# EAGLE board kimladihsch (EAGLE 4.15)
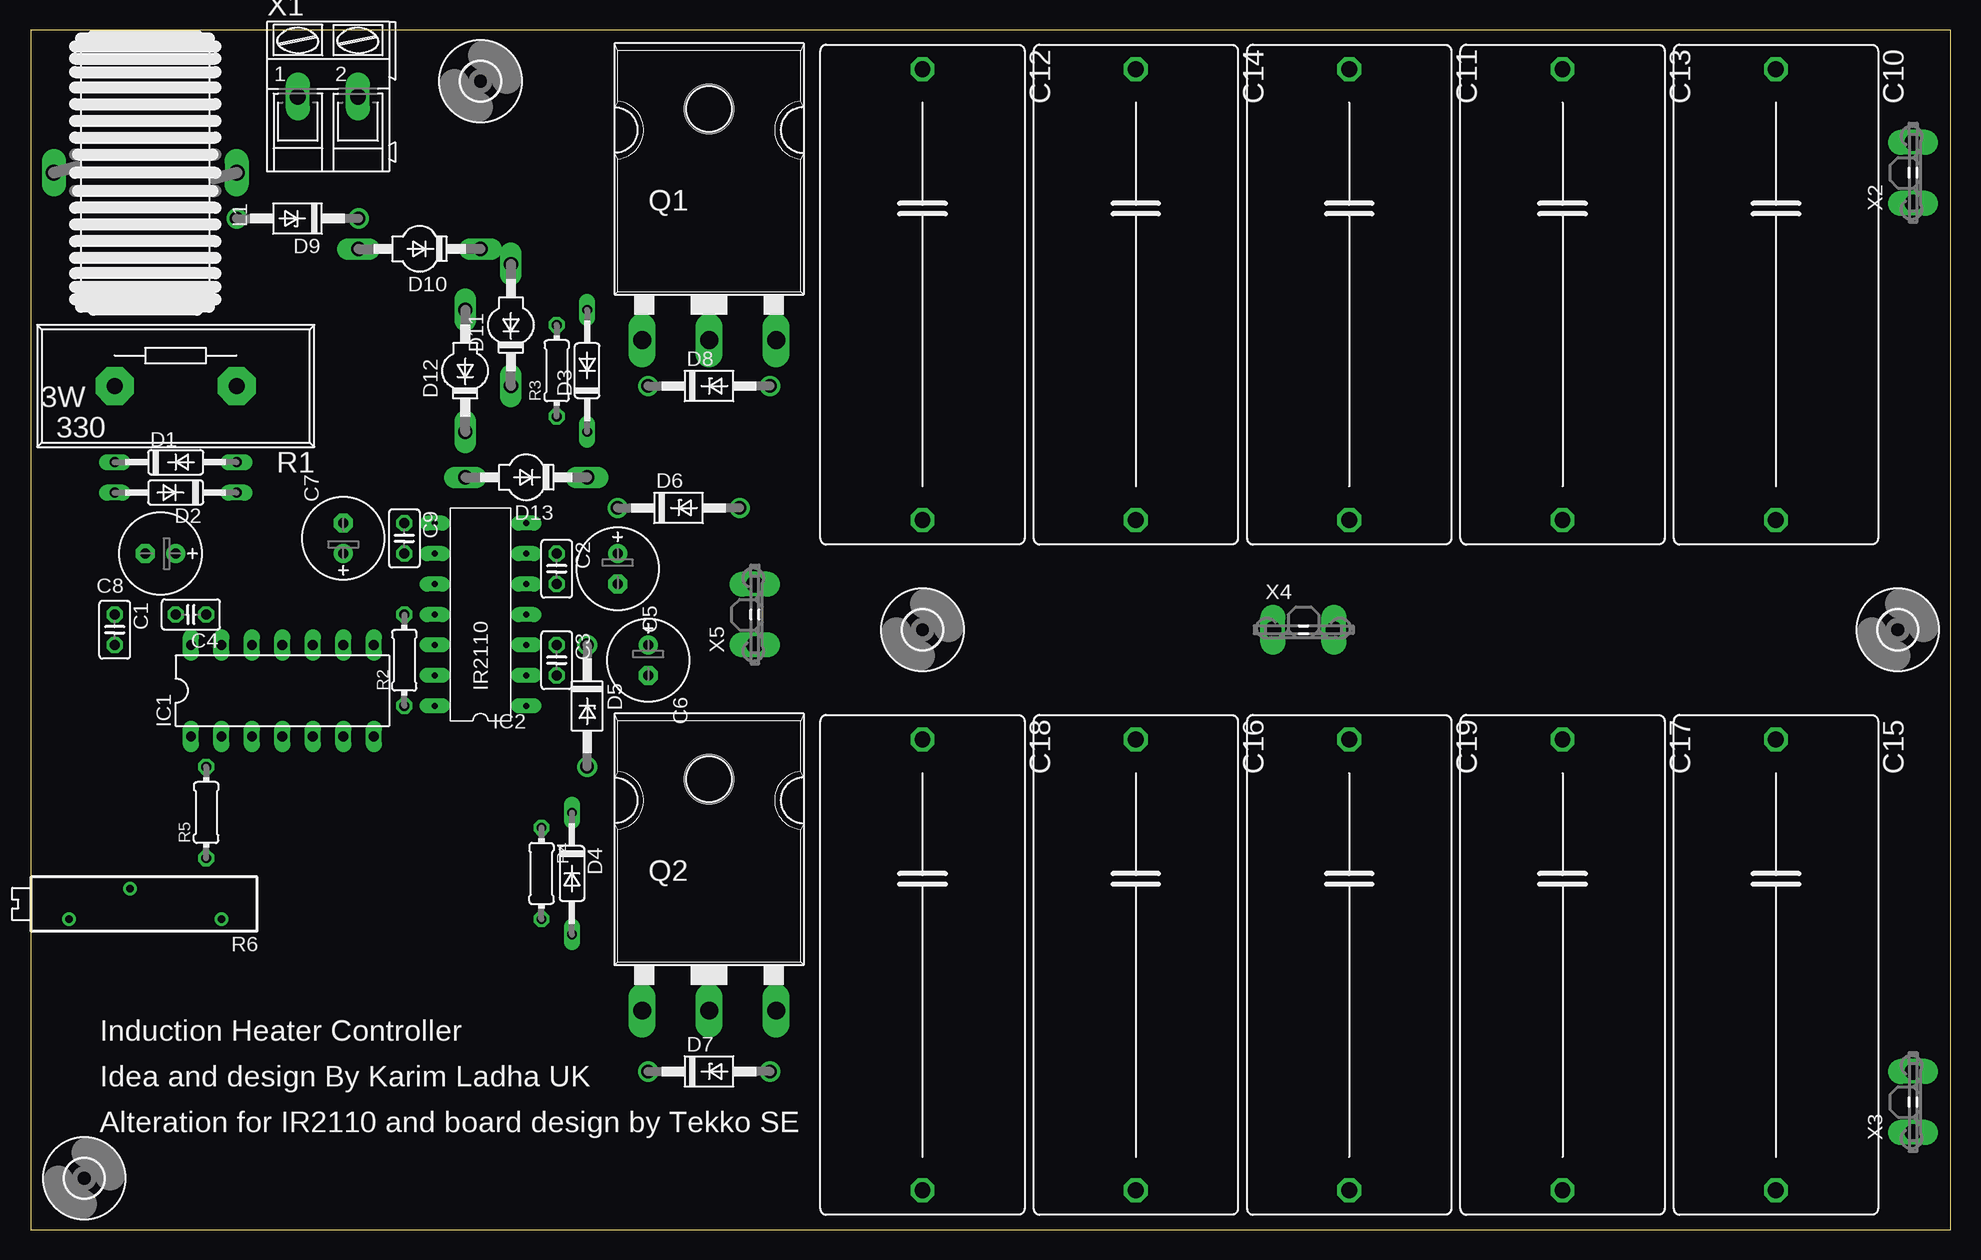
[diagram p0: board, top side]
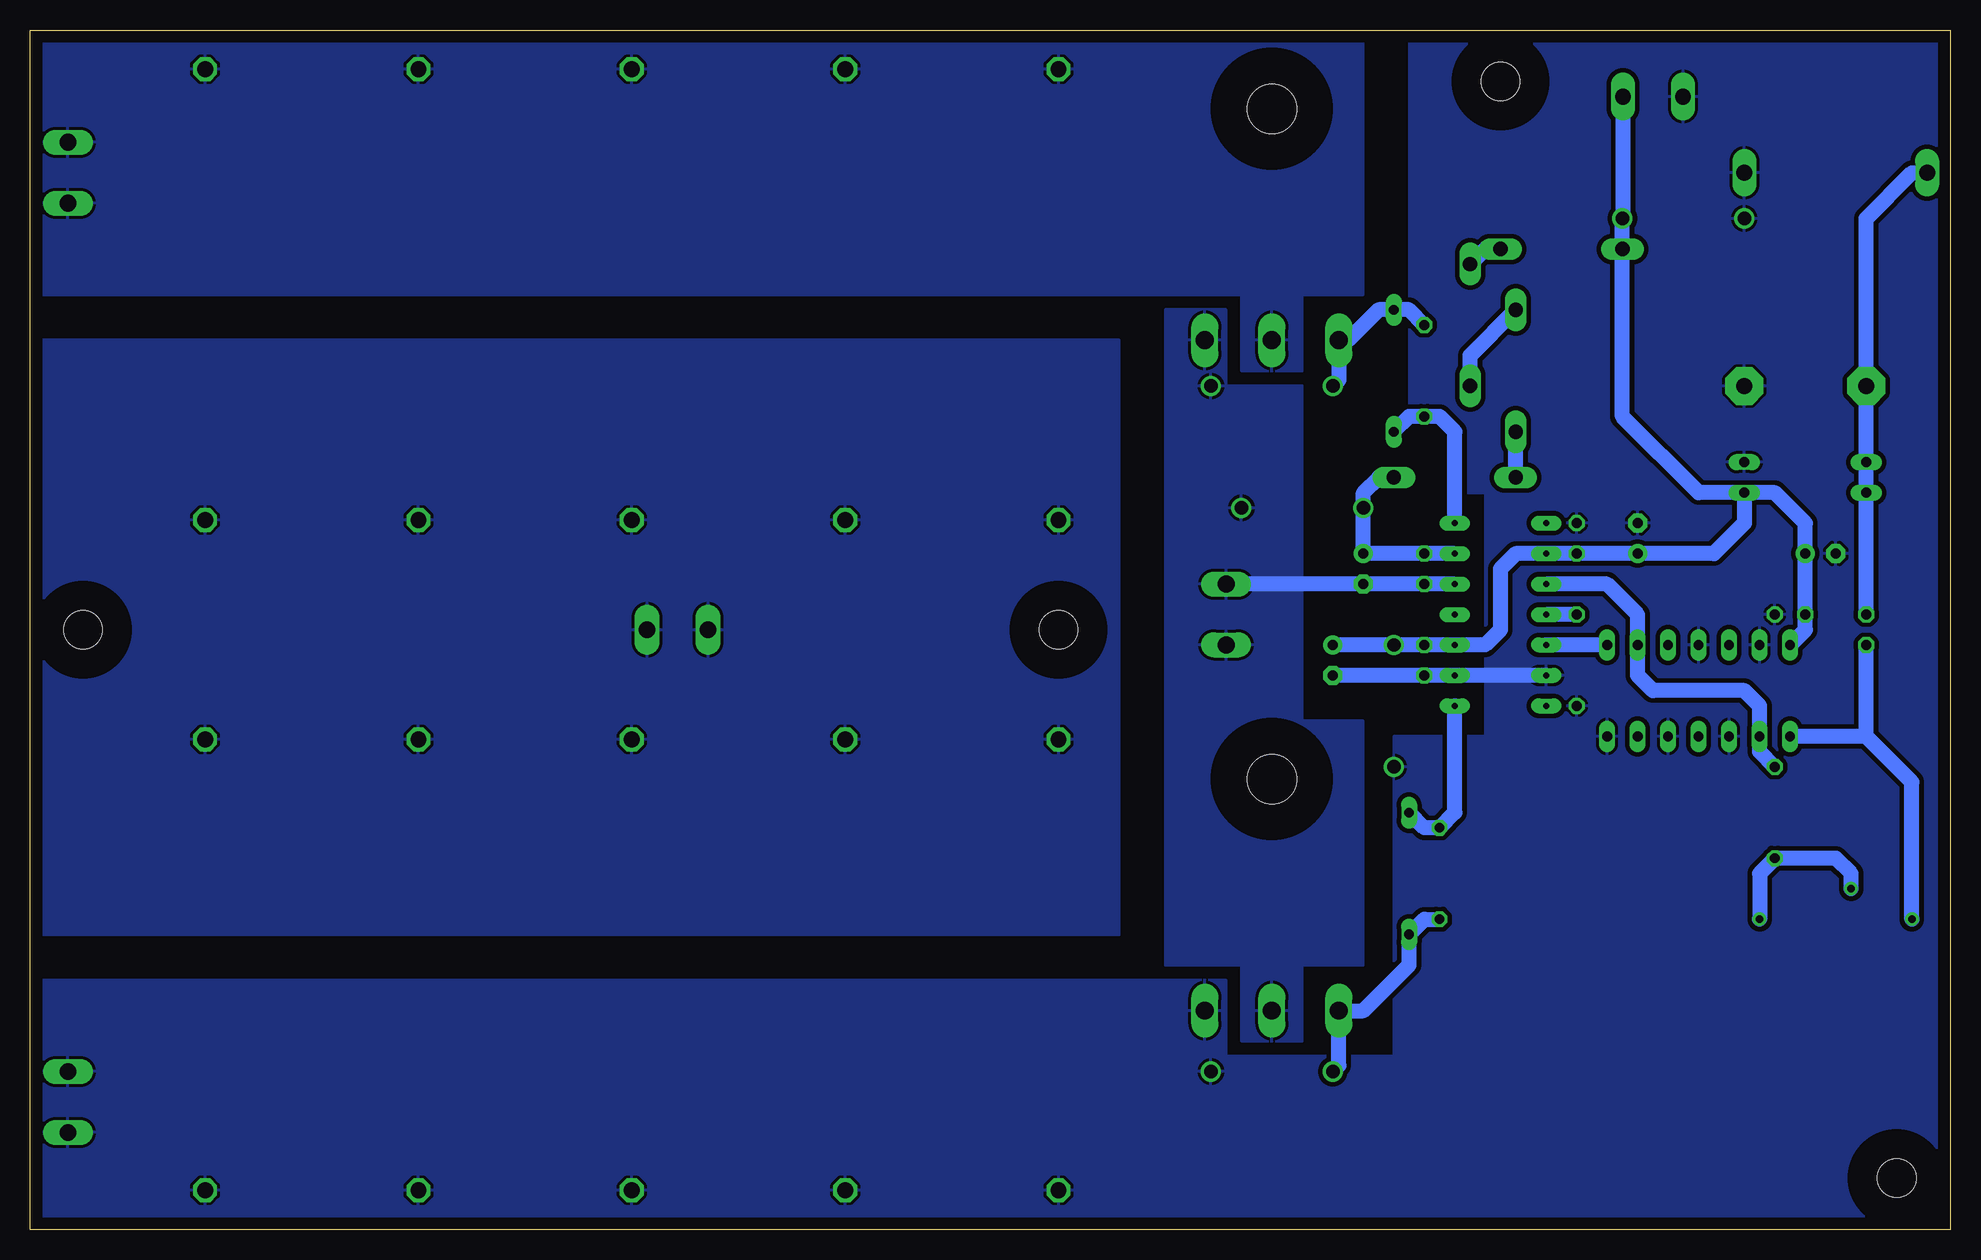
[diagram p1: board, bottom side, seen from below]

Size 160 x 100 mm. Coordinates in mm from the lower left corner, seen from the top.
Outline: 0,0 160,0 160,100 0,100 0,0
Copper layers (1*16): Top 0.035mm / dielectric 1.5mm / Bottom 0.035mm
Design rules "default": minimum track width 10mil, minimum drill 24mil, track to track 15mil, track to pad 15mil, pad to pad 15mil, via to via 15mil, smd to smd 8mil, copper to edge 40mil, drill to drill 8mil, minimum pad ring 10mil, minimum via ring 8mil, stop-mask expansion 4mil, vias tented up to drill 0mil, thermal gap 10mil

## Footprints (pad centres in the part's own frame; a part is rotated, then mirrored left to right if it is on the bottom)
C025-025X050 = drill 0.813 octagon: 1 -1.27,0; 2 1.27,0
E2,5-7 = drill 0.813 pad 1.6 round: + -1.27,0 | drill 0.813 pad 1.6 octagon: - 1.27,0
C375-192X418 = drill 1.321 octagon: 1 -18.796,0; 2 18.796,0
DO35-10 = drill 0.813 long: A 5.08,0; C -5.08,0
DO41Z10 = drill 1.118 round: A 5.08,0; C -5.08,0
SOD57-10 = drill 1.194 long: A 5.08,0; C -5.08,0
3,2 = hole 3.2: 0,0
DIL14 = drill 0.813 long: 1 -7.62,-3.81; 2 -5.08,-3.81; 3 -2.54,-3.81; 4 0,-3.81; 5 2.54,-3.81; 6 5.08,-3.81; 7 7.62,-3.81; 8 7.62,3.81; 9 5.08,3.81; 10 2.54,3.81; 11 0,3.81; 12 -2.54,3.81; 13 -5.08,3.81; 14 -7.62,3.81
DIL14' = drill 0.5 pad 1.27 long: 1 -2.54,-3.81; 2 0,-3.81; 3 2.54,-3.81; 4 5.08,-3.81; 5 7.62,-3.81; 6 10.16,-3.81; 7 12.7,-3.81; 8 12.7,3.81; 9 10.16,3.81; 10 7.62,3.81; 11 5.08,3.81; 12 2.54,3.81; 13 0,3.81; 14 -2.54,3.81
SFT1240 = drill 1.321 long: 1 -7.62,0; 2 7.62,0
TO247BH = drill 1.499 long: D 0,-10.16; G -5.588,-10.16; S 5.588,-10.16 | hole 4.115: 0,9.144
KWP330 = drill 1.321 pad 3.15 octagon: 1 -5.08,0; 2 5.08,0
0204/7 = drill 0.813 octagon: 1 -3.81,0; 2 3.81,0
RTRIM3006P = drill 0.61 round: 1 -7.62,1.27; 2 0,-1.27; 3 5.08,1.27
AK300/2 = drill 1.321 long: 1 -2.515,0; 2 2.489,0
ST6,3 = drill 1.397 long: 1 -2.54,0; 2 2.54,0

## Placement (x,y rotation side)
C1  [C025-025X050]  6.98,50 270 top
C2  [C025-025X050]  43.81,55.08 270 top
C3  [C025-025X050]  43.81,47.46 270 top
C4  [C025-025X050]  13.33,51.27 180 top
C5  [E2,5-7]  48.89,55.08 270 top
C6  [E2,5-7]  51.43,47.46 270 top
C7  [E2,5-7]  26.03,57.62 90 top
C8  [E2,5-7]  10.79,56.35 180 top
C9  [C025-025X050]  31.11,57.62 270 top
C10  [C375-192X418]  145.41,77.94 270 top
C11  [C375-192X418]  109.85,77.94 270 top
C12  [C375-192X418]  74.29,77.94 270 top
C13  [C375-192X418]  127.63,77.94 270 top
C14  [C375-192X418]  92.07,77.94 270 top
C15  [C375-192X418]  145.41,22.06 270 top
C16  [C375-192X418]  92.07,22.06 270 top
C17  [C375-192X418]  127.63,22.06 270 top
C18  [C375-192X418]  74.29,22.06 270 top
C19  [C375-192X418]  109.85,22.06 270 top
D1  1N4148  [DO35-10]  12.06,63.97 0 top
D2  1N4148  [DO35-10]  12.06,61.43 180 top
D3  1N4148  [DO35-10]  46.35,71.59 90 top
D4  1N4148  [DO35-10]  45.08,29.68 270 top
D5  BZX85  [DO41Z10]  46.35,43.65 270 top
D6  BZX85  [DO41Z10]  53.97,60.16 0 top
D7  BZX85  [DO41Z10]  56.51,13.17 0 top
D8  BZX85  [DO41Z10]  56.51,70.32 0 top
D9  BZX85  [DO41Z10]  22.22,84.29 180 top
D10  BYV27  [SOD57-10]  32.38,81.75 180 top
D11  BYV27  [SOD57-10]  40,75.4 90 top
D12  BYV27  [SOD57-10]  36.19,71.59 90 top
D13  BYV27  [SOD57-10]  41.27,62.7 180 top
H1  MOUNT-HOLE3.2  [3,2]  4.44,4.28 0 top
H2  MOUNT-HOLE3.2  [3,2]  37.46,95.72 0 top
H3  MOUNT-HOLE3.2  [3,2]  74.29,50 0 top
H4  MOUNT-HOLE3.2  [3,2]  155.57,50 0 top
IC1  40106N  [DIL14]  20.95,44.92 0 top
IC2  IR2110  [DIL14']  37.46,46.19 90 top
L1  1:100  [SFT1240]  9.52,88.1 180 top
Q1  HGTG20N60A4D  [TO247BH]  56.51,84.29 0 top
Q2  HGTG20N60A4D  [TO247BH]  56.51,28.41 0 top
R1  [KWP330]  12.06,70.32 180 top
R2  [0204/7]  31.11,47.46 90 top
R3  [0204/7]  43.81,71.59 90 top
R4  [0204/7]  42.54,29.68 270 top
R5  [0204/7]  14.6,34.76 90 top
R6  [RTRIM3006P]  8.25,27.14 180 top
X1  [AK300/2]  24.76,94.45 0 top
X2  [ST6,3]  156.84,88.1 90 top
X3  [ST6,3]  156.84,10.63 90 top
X4  [ST6,3]  106.04,50 0 top
X5  [ST6,3]  60.32,51.27 90 top

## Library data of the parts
C1-C19 R2-R6 = rcl
D1-D13 = diode
H1-H4 = holes
IC1 = 40xx
IC2 = ir2112
L1 = inductors
Q1 Q2 = transistor-power
R1 = resistor-power
X1 = con-ptr500
X2-X5 = con-rib

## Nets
+15V: C3.1 C4.2 C6.+ C7.+ C8.+ C9.2 D2.C D5.C D9.C D10.A IC1.14 IC2.3 IC2.9 X1.2
GND: C3.2 C4.1 C6.- C7.- C8.- C9.1 C15.2 C16.2 C17.2 C18.2 C19.2 D1.A D5.A D7.A D9.A IC1.3 IC1.5 IC1.7 IC1.11 IC1.13 IC2.2 IC2.13 L1.1 Q2.S R1.1 R2.1 X1.1 X3.1 X3.2
N$2: C1.1 D1.C D2.A L1.2 R1.2
N$3: C1.2 IC1.1 R6.3
N$4: IC1.2 IC1.9 IC2.10 R5.2
N$5: IC1.8 IC2.12
N$6: IC2.11 R2.2
N$11: D4.C IC2.1 R4.1
N$12: D4.A D7.C Q2.G R4.2
N$13: D3.C IC2.7 R3.1
N$14: D3.A D8.C Q1.G R3.2
N$20: D12.C D13.A
N$21: D11.C D12.A
N$22: D10.C D11.A
N$23: R5.1 R6.1 R6.2
RETURN: C10.2 C11.2 C12.2 C13.2 C14.2 C15.1 C16.1 C17.1 C18.1 C19.1 X4.1 X4.2
V+: C10.1 C11.1 C12.1 C13.1 C14.1 Q1.D X2.1 X2.2
VB: C2.1 C5.+ D6.C D13.C IC2.6
VS: C2.2 C5.- D6.A D8.A IC2.5 Q1.S Q2.D X5.1 X5.2

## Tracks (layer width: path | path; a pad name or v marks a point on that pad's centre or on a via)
+15V
  Bottom 1.27: X1.2 27.25,84.34 D9.C D10.A 27.3,67.78 20.95,61.43 D2.C | IC1.14 12.06,50 C4.2 C8.+ 12.06,58.89 14.6,61.43 D2.C | D2.C 17.14,58.89 19.68,56.35 C7.+ C9.2 IC2.9 36.19,56.35 37.46,55.08 37.46,50 38.73,48.73 IC2.3 C3.1 D5.C C6.+
GND
  Bottom 1.27: IC2.13 IC2.2 C3.2 C6.-
  pour Bottom: -0.64,100.8 45.08,100.8 45.08,61.43 38.73,61.43 38.73,41.11 46.35,41.11 46.35,14.44 60.32,14.44 60.32,20.79 64.13,20.79 62.86,20.79 160.65,20.79 160.65,-2.07 -0.64,-2.07
N$2
  Bottom 1.27: C1.1 D2.A D1.C R1.2 6.98,84.29 3.17,88.1 L1.2
N$3
  Bottom 1.27: R6.3 3.17,37.3 6.98,41.11 | 6.98,41.11 C1.2 | 6.98,41.11 IC1.1
N$4
  Bottom 1.27: IC2.10 28.57,53.81 26.03,51.27 IC1.9 26.03,46.19 24.76,44.92 17.14,44.92 15.87,43.65 IC1.2 15.87,39.84 R5.2
N$5
  Bottom 1.27: IC1.8 IC2.12
N$6
  Bottom 1.27: R2.2 IC2.11
N$11
  Bottom 1.27: IC2.1 41.27,34.76 R4.1 43.81,33.49 D4.C
N$12
  Bottom 1.27: R4.2 43.81,25.87 D4.A 45.08,22.06 48.89,18.25 Q2.G | Q2.G 51.43,18.25 | Q2.G 50.92,13.68 D7.C
N$13
  Bottom 1.27: IC2.7 41.27,66.51 42.54,67.78 R3.1 45.08,67.78 D3.C
N$14
  Bottom 1.27: R3.2 45.08,76.67 D3.A 47.62,76.67 50.16,74.13 Q1.G 50.92,70.83 D8.C
N$20
  Bottom 1.27: D13.A D12.C
N$21
  Bottom 1.27: D12.A 40,72.86 D11.C
N$22
  Bottom 1.27: D10.C 38.73,81.75 D11.A
N$23
  Bottom 1.27: R6.1 15.87,29.68 R5.1 9.52,30.95 8.25,29.68 R6.2
RETURN
  pour Bottom: 69.21,74.13 160.65,74.13 160.65,24.6 69.21,24.6
V+
  pour Bottom: 48.89,100.8 160.65,100.8 160.65,77.94 59.05,77.94 59.05,71.59 53.97,71.59 53.97,77.94 48.89,77.94
VB
  Bottom 1.27: IC2.6 C2.1 C5.+ D6.C 48.89,61.43 47.62,62.7 D13.C
VS
  Bottom 1.27: IC2.5 C2.2 C5.- X5.2
  pour Bottom: 60.32,76.67 65.4,76.67 65.4,22.06 59.05,22.06 59.05,15.71 53.97,15.71 53.97,22.06 48.89,22.06 48.89,42.38 53.97,42.38 53.97,70.32 60.32,70.32

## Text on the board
tPlace: Induction Heater Controller | Idea and design By Karim Ladha UK | Alteration for IR2110 and board design by Tekko SE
